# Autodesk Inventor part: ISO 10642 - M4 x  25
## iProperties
Library Location: D:\Prog\Autodesk\Inventor 6\content
Library: local
SubLibrary: ISO
Family: 3
Member: 16
Member Major Revision: 1
Member Minor Revision: 1
Comments: To add or edit properties for Autodesk Inventor files, use iProperties.
Created: 2003-06
Part Number: ISO 10642 - M4 x  25
Vendor: Autodesk Inc.
Document SubType Name: Modeling
Designer: JB
Description: Hexagon Socket Countersunk Head Screw
Standard: ISO 10642 M4 x  25
Alert: To add or edit properties for Autodesk Inventor files, use iProperties.
Control State: 0
Master: False
Checked Out: False
Shininess: 64.0
Length Units: 11269
Angle Units: 11279
Time Units: 11290
Mass Units: 11283
Length Display Precision: 3
Angle Display Precision: 2
Compacted: True
EGR: 1
Density: 0.0
Volumn: 0.0
Area: 0.0
PropertySet Name: Model Information
Author: JB
Revision Number: 1
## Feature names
1. Body [Revolution]
2. Slot [Extrusion]
3. Chamfer1
